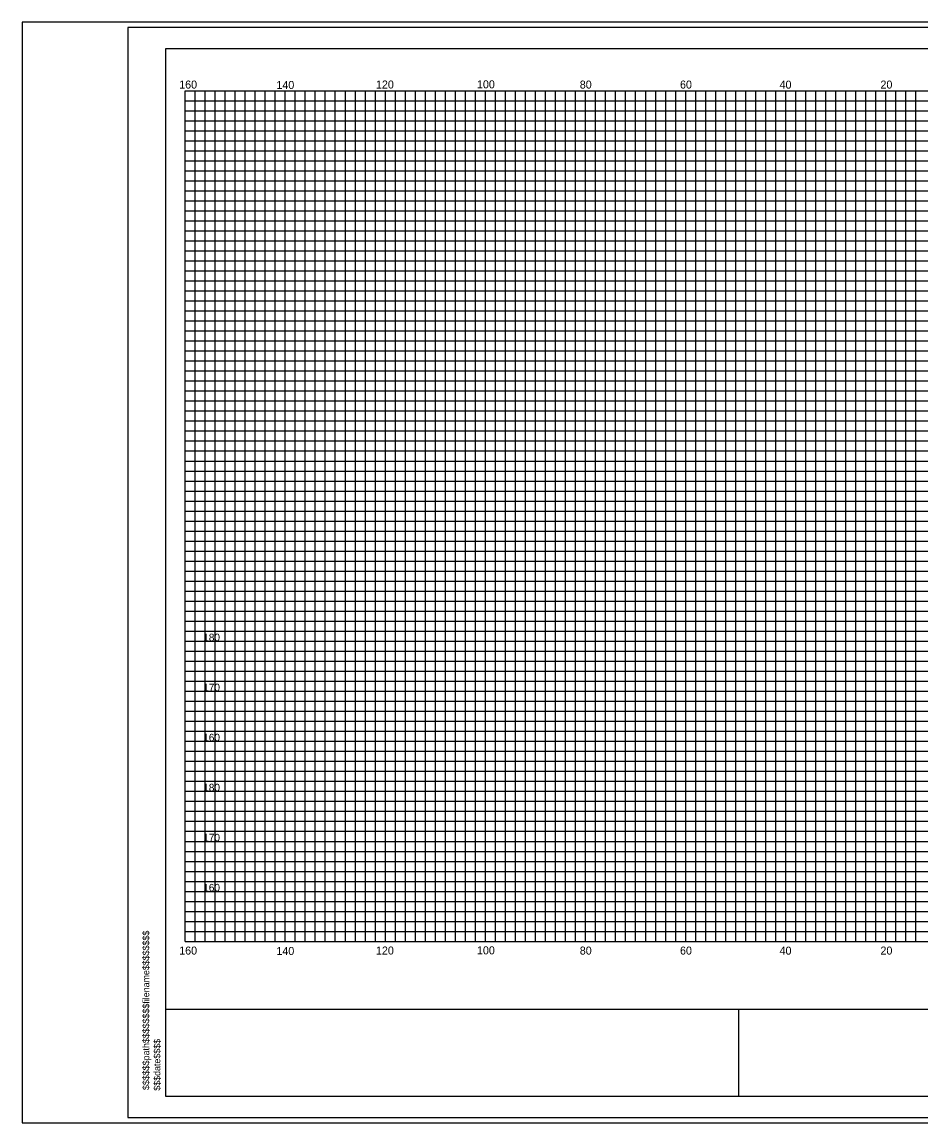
# Model space of a CAD drawing. Extents: x 967 to 1326, y 964 to 2864.
# Drawn here: x 967.4 to 1147, y 2643.7 to 2863.7 of the extents above; entities that cross this region are included whole.
import ezdxf

# ---------------------------------------------------------------- set-up
doc = ezdxf.new("R2010")
doc.units = 0
for name, color, linetype in [('Default', 7, 'Continuous'), ('RD_EX_RW', 7, 'Continuous'), ('RD_PD_Final_TX', 7, 'Continuous'), ('RD_SHT_ShtClip', 7, 'Continuous'), ('RD_XS_TX_Elev_PR', 7, 'Continuous'), ('RD_XS_TX_Slope', 7, 'Continuous')]:
    doc.layers.add(name, color=color, linetype=linetype)

msp = doc.modelspace()

# ---------------------------------------------------------------- linework, layer by layer
at = {"layer": 'RD_EX_RW'}
for p, q in [((1000, 2850), (1320, 2850)), ((1000, 2680), (1000, 2850)), ((1010, 2680), (1010, 2850)), ((1020, 2680), (1020, 2850)), ((1030, 2680), (1030, 2850)), ((1040, 2680), (1040, 2850)), ((1050, 2680), (1050, 2850)), ((1060, 2680), (1060, 2850)), ((1070, 2680), (1070, 2850)), ((1080, 2680), (1080, 2850)), ((1090, 2680), (1090, 2850)), ((1100, 2680), (1100, 2850)), ((1110, 2680), (1110, 2850)), ((1120, 2680), (1120, 2850)), ((1130, 2680), (1130, 2850)), ((1140, 2680), (1140, 2850)), ((1000, 2840), (1320, 2840)), ((1000, 2830), (1320, 2830)), ((1000, 2820), (1320, 2820)), ((1000, 2810), (1320, 2810)), ((1000, 2800), (1320, 2800)), ((1000, 2790), (1320, 2790)), ((1000, 2780), (1320, 2780)), ((1000, 2770), (1320, 2770)), ((1000, 2760), (1320, 2760)), ((1000, 2750), (1320, 2750)), ((1000, 2740), (1320, 2740)), ((1000, 2730), (1320, 2730)), ((1000, 2720), (1320, 2720)), ((1000, 2710), (1320, 2710)), ((1000, 2700), (1320, 2700)), ((1000, 2690), (1320, 2690)), ((1000, 2680), (1320, 2680))]:
    msp.add_line(p, q, dxfattribs=at)
at = {"layer": 'RD_PD_Final_TX'}
for p, q in [((996.11, 2648.98), (996.11, 2858.46)), ((996.11, 2858.46), (1323.89, 2858.46)), ((996.11, 2666.49), (1323.89, 2666.49)), ((1110.59, 2648.98), (1110.59, 2666.56)), ((1323.89, 2648.98), (996.11, 2648.98))]:
    msp.add_line(p, q, dxfattribs=at)
at = {"layer": 'RD_SHT_ShtClip'}
for p, q in [((1002, 2680), (1002, 2850)), ((1004, 2680), (1004, 2850)), ((1006, 2680), (1006, 2850)), ((1008, 2680), (1008, 2850)), ((1012, 2680), (1012, 2850)), ((1014, 2680), (1014, 2850)), ((1016, 2680), (1016, 2850)), ((1018, 2680), (1018, 2850)), ((1022, 2680), (1022, 2850)), ((1024, 2680), (1024, 2850)), ((1026, 2680), (1026, 2850)), ((1028, 2680), (1028, 2850)), ((1032, 2680), (1032, 2850)), ((1034, 2680), (1034, 2850)), ((1036, 2680), (1036, 2850)), ((1038, 2680), (1038, 2850)), ((1042, 2680), (1042, 2850)), ((1044, 2680), (1044, 2850)), ((1046, 2680), (1046, 2850)), ((1048, 2680), (1048, 2850)), ((1052, 2680), (1052, 2850)), ((1054, 2680), (1054, 2850)), ((1056, 2680), (1056, 2850)), ((1058, 2680), (1058, 2850)), ((1062, 2680), (1062, 2850)), ((1064, 2680), (1064, 2850)), ((1066, 2680), (1066, 2850)), ((1068, 2680), (1068, 2850)), ((1072, 2680), (1072, 2850)), ((1074, 2680), (1074, 2850)), ((1076, 2680), (1076, 2850)), ((1078, 2680), (1078, 2850)), ((1082, 2680), (1082, 2850)), ((1084, 2680), (1084, 2850)), ((1086, 2680), (1086, 2850)), ((1088, 2680), (1088, 2850)), ((1092, 2680), (1092, 2850)), ((1094, 2680), (1094, 2850)), ((1096, 2680), (1096, 2850)), ((1098, 2680), (1098, 2850)), ((1102, 2680), (1102, 2850)), ((1104, 2680), (1104, 2850)), ((1106, 2680), (1106, 2850)), ((1108, 2680), (1108, 2850)), ((1112, 2680), (1112, 2850)), ((1114, 2680), (1114, 2850)), ((1116, 2680), (1116, 2850)), ((1118, 2680), (1118, 2850)), ((1122, 2680), (1122, 2850)), ((1124, 2680), (1124, 2850)), ((1126, 2680), (1126, 2850)), ((1128, 2680), (1128, 2850)), ((1132, 2680), (1132, 2850)), ((1134, 2680), (1134, 2850)), ((1136, 2680), (1136, 2850)), ((1138, 2680), (1138, 2850)), ((1142, 2680), (1142, 2850)), ((1144, 2680), (1144, 2850)), ((1146, 2680), (1146, 2850)), ((1000, 2848), (1320, 2848)), ((1000, 2846), (1320, 2846)), ((1000, 2844), (1320, 2844)), ((1000, 2842), (1320, 2842)), ((1000, 2838), (1320, 2838)), ((1000, 2836), (1320, 2836)), ((1000, 2834), (1320, 2834)), ((1000, 2832), (1320, 2832)), ((1000, 2828), (1320, 2828)), ((1000, 2826), (1320, 2826)), ((1000, 2824), (1320, 2824)), ((1000, 2822), (1320, 2822)), ((1000, 2818), (1320, 2818)), ((1000, 2816), (1320, 2816)), ((1000, 2814), (1320, 2814)), ((1000, 2812), (1320, 2812)), ((1000, 2808), (1320, 2808)), ((1000, 2806), (1320, 2806)), ((1000, 2804), (1320, 2804)), ((1000, 2802), (1320, 2802)), ((1000, 2798), (1320, 2798)), ((1000, 2796), (1320, 2796)), ((1000, 2794), (1320, 2794)), ((1000, 2792), (1320, 2792)), ((1000, 2788), (1320, 2788)), ((1000, 2786), (1320, 2786)), ((1000, 2784), (1320, 2784)), ((1000, 2782), (1320, 2782)), ((1000, 2778), (1320, 2778)), ((1000, 2776), (1320, 2776)), ((1000, 2774), (1320, 2774)), ((1000, 2772), (1320, 2772)), ((1000, 2768), (1320, 2768)), ((1000, 2766), (1320, 2766)), ((1000, 2764), (1320, 2764)), ((1000, 2762), (1320, 2762)), ((1000, 2758), (1320, 2758)), ((1000, 2756), (1320, 2756)), ((1000, 2754), (1320, 2754)), ((1000, 2752), (1320, 2752)), ((1000, 2748), (1320, 2748)), ((1000, 2746), (1320, 2746)), ((1000, 2744), (1320, 2744)), ((1000, 2742), (1320, 2742)), ((1000, 2738), (1320, 2738)), ((1000, 2736), (1320, 2736)), ((1000, 2734), (1320, 2734)), ((1000, 2732), (1320, 2732)), ((1000, 2728), (1320, 2728)), ((1000, 2726), (1320, 2726)), ((1000, 2724), (1320, 2724)), ((1000, 2722), (1320, 2722)), ((1000, 2718), (1320, 2718)), ((1000, 2716), (1320, 2716)), ((1000, 2714), (1320, 2714)), ((1000, 2712), (1320, 2712)), ((1000, 2708), (1320, 2708)), ((1000, 2706), (1320, 2706)), ((1000, 2704), (1320, 2704)), ((1000, 2702), (1320, 2702)), ((1000, 2698), (1320, 2698)), ((1000, 2696), (1320, 2696)), ((1000, 2694), (1320, 2694)), ((1000, 2692), (1320, 2692)), ((1000, 2688), (1320, 2688)), ((1000, 2686), (1320, 2686)), ((1000, 2684), (1320, 2684)), ((1000, 2682), (1320, 2682))]:
    msp.add_line(p, q, dxfattribs=at)
at = {"layer": 'RD_XS_TX_Elev_PR'}
for points in [[(967.41, 2643.72), (1326.28, 2643.72), (1326.28, 2863.72), (967.41, 2863.72)], [(988.52, 2644.84), (1326.28, 2644.84), (1326.28, 2862.6), (988.52, 2862.6)]]:
    msp.add_lwpolyline(points, close=True, dxfattribs=at)

# ---------------------------------------------------------------- texts
at = {"layer": 'Default'}
for s, p in [('180', (1003.61, 2740)), ('170', (1003.61, 2730)), ('160', (1003.61, 2720)), ('180', (1003.61, 2710)), ('170', (1003.61, 2700)), ('160', (1003.61, 2690))]:
    msp.add_text(s, height=1.5, dxfattribs=at).set_placement(p)
for s, p in [('$$$$$$path$$$$$$$$filename$$$$$$$$', (992.83, 2650.31)), ('$$$date$$$$', (995.04, 2650.17))]:
    msp.add_text(s, height=1.3258, rotation=90, dxfattribs=at).set_placement(p)
at = {"layer": 'RD_XS_TX_Slope'}
for s, p in [('160', (998.81, 2850.42)), ('140', (1018.23, 2850.34)), ('120', (1038.12, 2850.43)), ('100', (1058.3, 2850.47)), ('80', (1078.84, 2850.42)), ('60', (1098.86, 2850.42)), ('40', (1118.75, 2850.41)), ('20', (1138.91, 2850.42)), ('160', (998.81, 2677.37)), ('140', (1018.23, 2677.29)), ('120', (1038.12, 2677.38)), ('100', (1058.3, 2677.42)), ('80', (1078.84, 2677.37)), ('60', (1098.86, 2677.37)), ('40', (1118.75, 2677.36)), ('20', (1138.91, 2677.37))]:
    msp.add_text(s, height=1.6, dxfattribs=at).set_placement(p)

doc.saveas('drawing.dxf')
